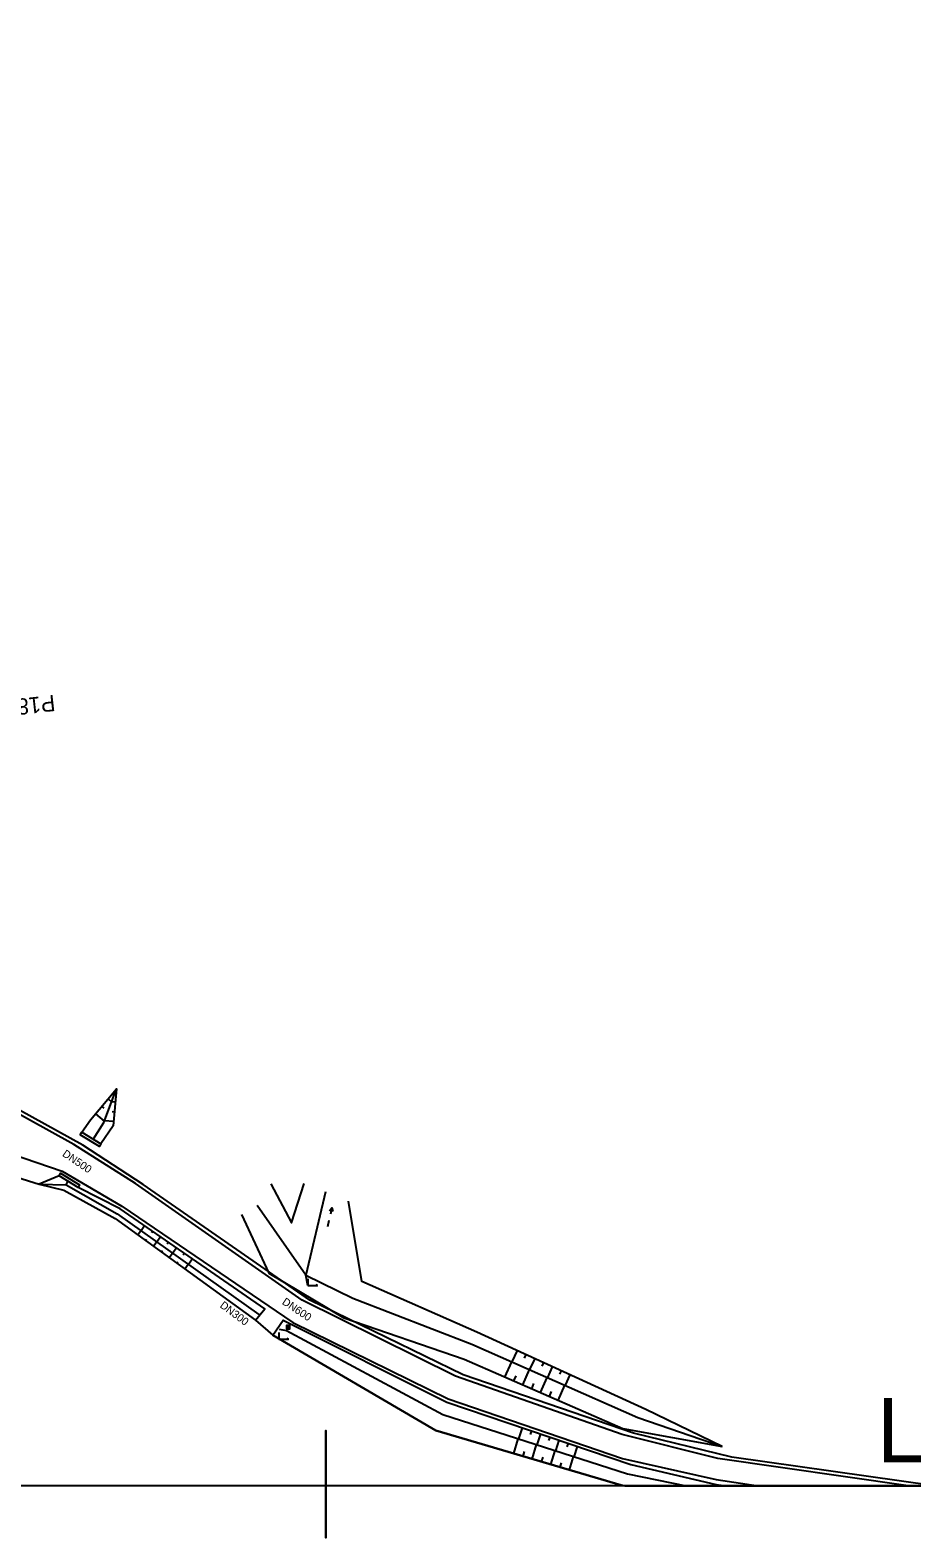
# Model space of a CAD drawing. Extents: x -574342 to -507939, y -1144044 to -1123894.
# Drawn here: x -508492.5 to -508356.1, y -1144043.8 to -1143810.6 of the extents above; entities that cross this region are included whole.
import ezdxf

# ---------------------------------------------------------------- set-up
doc = ezdxf.new("R2010")
doc.units = 0
for name, color, linetype in [('01_PARCELY_NAVRH_PC', 7, 'Continuous'), ('03_PC_POPIS_STAV', 7, 'Continuous'), ('15', 7, 'Continuous'), ('19', 7, 'Continuous'), ('43', 7, 'Continuous'), ('52', 7, 'Continuous'), ('55', 7, 'Continuous'), ('57', 7, 'Continuous'), ('60', 7, 'Continuous'), ('61', 7, 'Continuous'), ('Level 1', 7, 'Continuous')]:
    doc.layers.add(name, color=color, linetype=linetype)

msp = doc.modelspace()

# ---------------------------------------------------------------- linework, layer by layer
msp.add_lwpolyline([(-508446.76, -1144027.14), (-508446.76, -1144027.14), (-508446.76, -1144043.76), (-508446.76, -1144043.76)], close=True)
msp.add_lwpolyline([(-508446.76, -1144027.14), (-508446.76, -1144027.14), (-508446.76, -1144043.76), (-508446.76, -1144043.76)], close=True)
at = {"layer": '01_PARCELY_NAVRH_PC'}
msp.add_line((-508400.5, -1144035.7), (-508352.57, -1144035.7), dxfattribs=at)
for points in [[(-508352.57, -1144035.7), (-508383.92, -1144031.28), (-508399.15, -1144027.55), (-508425.48, -1144018.52), (-508449.21, -1144007), (-508475, -1143989.08), (-508484.35, -1143983.03), (-508505.5, -1143971.38)], [(-508500.67, -1143986.05), (-508491.07, -1143989.03), (-508487.29, -1143989.98), (-508479.33, -1143994.34), (-508457.64, -1144010.1), (-508454.94, -1144012.4), (-508429.75, -1144027.17), (-508401.07, -1144035.61), (-508400.5, -1144035.7)]]:
    msp.add_lwpolyline(points, dxfattribs=at)
at = {"layer": '43'}
for p, q in [((-508445.81, -1143992.73), (-508446.04, -1143993.7)), ((-508446.27, -1143994.67), (-508446.5, -1143995.65))]:
    msp.add_line(p, q, dxfattribs=at)
msp.add_lwpolyline([(-508446.16, -1143993.16), (-508445.81, -1143992.73), (-508445.68, -1143993.27)], dxfattribs=at)
at = {"layer": '52'}
for p, q in [((-508449.54, -1144003.7), (-508449.54, -1144004.7)), ((-508449.54, -1144004.7), (-508448.04, -1144004.7)), ((-508448.04, -1144004.7), (-508448.29, -1144004.6)), ((-508448.04, -1144004.7), (-508448.29, -1144004.8)), ((-508454.04, -1144012), (-508454.04, -1144013)), ((-508454.04, -1144013), (-508452.54, -1144013)), ((-508452.82, -1144011.17), (-508452.32, -1144011.17)), ((-508452.54, -1144013), (-508452.79, -1144012.9)), ((-508452.54, -1144013), (-508452.79, -1144013.1))]:
    msp.add_line(p, q, dxfattribs=at)
msp.add_lwpolyline([(-508452.82, -1144011.42), (-508452.32, -1144011.42), (-508452.32, -1144010.92), (-508452.82, -1144010.92)], close=True, dxfattribs=at)
at = {"layer": '55'}
for points in [[(-508356.68, -1144035.7), (-508386.12, -1144031.46), (-508400.9, -1144027.79), (-508426.7, -1144018.73), (-508450.39, -1144006.99), (-508476.21, -1143988.97), (-508485.71, -1143982.94), (-508506.36, -1143971.52), (-508511.83, -1143966.66), (-508520.4, -1143955.08), (-508524.66, -1143946.72), (-508527.67, -1143936.89)], [(-508356.68, -1144035.7), (-508386.12, -1144031.46), (-508400.9, -1144027.79), (-508426.7, -1144018.73), (-508450.39, -1144006.99), (-508476.21, -1143988.97), (-508485.71, -1143982.94), (-508506.36, -1143971.52), (-508511.83, -1143966.66), (-508520.4, -1143955.08), (-508524.66, -1143946.72), (-508527.67, -1143936.89)], [(-508494.55, -1144035.7), (-508500.53, -1144003.94), (-508501.48, -1143990.48), (-508500.5, -1143985.91), (-508495.36, -1143984.38), (-508487.51, -1143987.06), (-508478.31, -1143992.46), (-508451.87, -1144010.46), (-508427.81, -1144022.28), (-508400.84, -1144031.49), (-508386.35, -1144034.74), (-508379.88, -1144035.7)], [(-508494.55, -1144035.7), (-508500.53, -1144003.94), (-508501.48, -1143990.48), (-508500.5, -1143985.91), (-508495.36, -1143984.38), (-508487.51, -1143987.06), (-508478.31, -1143992.46), (-508451.87, -1144010.46), (-508427.81, -1144022.28), (-508400.84, -1144031.49), (-508386.35, -1144034.74), (-508379.88, -1144035.7)]]:
    msp.add_lwpolyline(points, dxfattribs=at)
at = {"layer": '57'}
for points in [[(-508484.75, -1143981.4), (-508484.5, -1143981.01), (-508481.54, -1143982.82), (-508481.77, -1143983.21)], [(-508484.75, -1143981.4), (-508484.5, -1143981.01), (-508481.54, -1143982.82), (-508481.77, -1143983.21)], [(-508488.01, -1143987.76), (-508487.79, -1143987.34), (-508484.84, -1143989.15), (-508485.07, -1143989.55)], [(-508488.01, -1143987.76), (-508487.79, -1143987.34), (-508484.84, -1143989.15), (-508485.07, -1143989.55)]]:
    msp.add_lwpolyline(points, close=True, dxfattribs=at)
at = {"layer": '60'}
for points in [[(-508484.5, -1143981.01), (-508483.17, -1143979.1), (-508479.13, -1143974.33), (-508479.65, -1143980.03), (-508481.54, -1143982.82)], [(-508484.5, -1143981.01), (-508483.17, -1143979.1), (-508479.13, -1143974.33), (-508479.65, -1143980.03), (-508481.54, -1143982.82)], [(-508482.7, -1143982.05), (-508481.08, -1143979.49), (-508479.13, -1143974.33)], [(-508482.7, -1143982.05), (-508481.08, -1143979.49), (-508479.13, -1143974.33)], [(-508488.01, -1143987.76), (-508491.07, -1143989.03), (-508487.29, -1143989.98), (-508479.33, -1143994.34), (-508457.64, -1144010.1), (-508456.2, -1144008.33), (-508478.56, -1143992.86), (-508485.07, -1143989.55)], [(-508488.01, -1143987.76), (-508491.07, -1143989.03), (-508487.29, -1143989.98), (-508479.33, -1143994.34), (-508457.64, -1144010.1), (-508456.2, -1144008.33), (-508478.56, -1143992.86), (-508485.07, -1143989.55)], [(-508491.07, -1143989.03), (-508486.93, -1143989.14), (-508486.66, -1143988.63)], [(-508491.07, -1143989.03), (-508486.93, -1143989.14), (-508486.66, -1143988.63)], [(-508486.93, -1143989.14), (-508479, -1143993.65), (-508457.13, -1144009.2)], [(-508486.93, -1143989.14), (-508479, -1143993.65), (-508457.13, -1144009.2)], [(-508455.24, -1143989.01), (-508452.07, -1143995.01), (-508450.12, -1143988.95)], [(-508455.24, -1143989.01), (-508452.07, -1143995.01), (-508450.12, -1143988.95)], [(-508446.77, -1143990.23), (-508449.82, -1144003.12), (-508442.59, -1144006.66), (-508424.18, -1144013.79), (-508398.46, -1144025.13), (-508385.42, -1144029.63)], [(-508446.77, -1143990.23), (-508449.82, -1144003.12), (-508442.59, -1144006.66), (-508424.18, -1144013.79), (-508398.46, -1144025.13), (-508385.42, -1144029.63)], [(-508385.42, -1144029.63), (-508397.26, -1144023.91), (-508423.4, -1144011.92), (-508441.15, -1144004.09), (-508443.23, -1143991.68)], [(-508385.42, -1144029.63), (-508397.26, -1144023.91), (-508423.4, -1144011.92), (-508441.15, -1144004.09), (-508443.23, -1143991.68)], [(-508459.81, -1143993.72), (-508455.54, -1144002.83), (-508443.94, -1144009.73), (-508425.37, -1144016.1), (-508400.82, -1144026.86), (-508385.42, -1144029.63)], [(-508459.81, -1143993.72), (-508455.54, -1144002.83), (-508443.94, -1144009.73), (-508425.37, -1144016.1), (-508400.82, -1144026.86), (-508385.42, -1144029.63)], [(-508449.54, -1144004.7), (-508449.82, -1144003.12), (-508457.37, -1143992.34)], [(-508449.54, -1144004.7), (-508449.82, -1144003.12), (-508457.37, -1143992.34)], [(-508454.94, -1144012.4), (-508453.34, -1144010.07), (-508428.03, -1144022.77), (-508399.55, -1144032.43), (-508386.38, -1144035.48), (-508384.8, -1144035.7)], [(-508454.94, -1144012.4), (-508453.34, -1144010.07), (-508428.03, -1144022.77), (-508399.55, -1144032.43), (-508386.38, -1144035.48), (-508384.8, -1144035.7)], [(-508400.5, -1144035.7), (-508401.07, -1144035.61), (-508429.75, -1144027.17), (-508454.94, -1144012.4)], [(-508400.5, -1144035.7), (-508401.07, -1144035.61), (-508429.75, -1144027.17), (-508454.94, -1144012.4)], [(-508453.94, -1144011.46), (-508452.82, -1144011.66), (-508452.57, -1144011.17)], [(-508453.94, -1144011.46), (-508452.82, -1144011.66), (-508452.57, -1144011.17)], [(-508452.82, -1144011.66), (-508428.63, -1144024.66), (-508400.09, -1144033.88), (-508390.99, -1144035.7)], [(-508452.82, -1144011.66), (-508428.63, -1144024.66), (-508400.09, -1144033.88), (-508390.99, -1144035.7)]]:
    msp.add_lwpolyline(points, dxfattribs=at)
at = {"layer": '61'}
for p, q in [((-508481.4, -1143977.02), (-508481.09, -1143977.28)), ((-508481.4, -1143977.02), (-508481.09, -1143977.28)), ((-508480.43, -1143975.87), (-508479.89, -1143976.33)), ((-508480.43, -1143975.87), (-508479.89, -1143976.33)), ((-508479.32, -1143976.39), (-508479.89, -1143976.34)), ((-508479.32, -1143976.39), (-508479.89, -1143976.34)), ((-508479.45, -1143977.89), (-508479.78, -1143977.86)), ((-508479.45, -1143977.89), (-508479.78, -1143977.86)), ((-508482.37, -1143978.16), (-508481.01, -1143979.31)), ((-508482.37, -1143978.16), (-508481.01, -1143979.31)), ((-508479.59, -1143979.38), (-508480.99, -1143979.25)), ((-508479.59, -1143979.38), (-508480.99, -1143979.25)), ((-508475.83, -1143996.88), (-508475.36, -1143996.24)), ((-508475.83, -1143996.88), (-508475.36, -1143996.24)), ((-508474.78, -1143995.48), (-508475.32, -1143996.26)), ((-508474.78, -1143995.48), (-508475.32, -1143996.26)), ((-508473.54, -1143996.33), (-508473.73, -1143996.6)), ((-508473.54, -1143996.33), (-508473.73, -1143996.6)), ((-508474.62, -1143997.76), (-508474.46, -1143997.54)), ((-508474.62, -1143997.76), (-508474.46, -1143997.54)), ((-508473.41, -1143998.64), (-508472.92, -1143997.97)), ((-508473.41, -1143998.64), (-508472.92, -1143997.97)), ((-508472.31, -1143997.18), (-508472.88, -1143998)), ((-508472.31, -1143997.18), (-508472.88, -1143998)), ((-508471.08, -1143998.04), (-508471.27, -1143998.32)), ((-508471.08, -1143998.04), (-508471.27, -1143998.32)), ((-508469.84, -1143998.89), (-508470.43, -1143999.74)), ((-508469.84, -1143998.89), (-508470.43, -1143999.74)), ((-508472.19, -1143999.53), (-508472.03, -1143999.3)), ((-508472.19, -1143999.53), (-508472.03, -1143999.3)), ((-508470.98, -1144000.41), (-508470.47, -1143999.71)), ((-508470.98, -1144000.41), (-508470.47, -1143999.71)), ((-508469.77, -1144001.29), (-508469.59, -1144001.05)), ((-508469.77, -1144001.29), (-508469.59, -1144001.05)), ((-508468.61, -1143999.74), (-508468.81, -1144000.03)), ((-508468.61, -1143999.74), (-508468.81, -1144000.03)), ((-508467.38, -1144000.6), (-508467.99, -1144001.48)), ((-508467.38, -1144000.6), (-508467.99, -1144001.48)), ((-508468.55, -1144002.17), (-508468.03, -1144001.45)), ((-508468.55, -1144002.17), (-508468.03, -1144001.45)), ((-508417.16, -1144014.78), (-508417.96, -1144016.53)), ((-508417.16, -1144014.78), (-508417.96, -1144016.53)), ((-508419.03, -1144018.88), (-508417.99, -1144016.52)), ((-508419.03, -1144018.88), (-508417.99, -1144016.52)), ((-508415.8, -1144015.41), (-508416.06, -1144015.98)), ((-508415.8, -1144015.41), (-508416.06, -1144015.98)), ((-508414.43, -1144016.03), (-508415.22, -1144017.74)), ((-508414.43, -1144016.03), (-508415.22, -1144017.74)), ((-508413.07, -1144016.66), (-508413.33, -1144017.22)), ((-508413.07, -1144016.66), (-508413.33, -1144017.22)), ((-508411.71, -1144017.28), (-508412.47, -1144018.95)), ((-508411.71, -1144017.28), (-508412.47, -1144018.95)), ((-508417.65, -1144019.48), (-508417.31, -1144018.7)), ((-508417.65, -1144019.48), (-508417.31, -1144018.7)), ((-508416.28, -1144020.08), (-508415.25, -1144017.73)), ((-508416.28, -1144020.08), (-508415.25, -1144017.73)), ((-508414.9, -1144020.69), (-508414.56, -1144019.9)), ((-508414.9, -1144020.69), (-508414.56, -1144019.9)), ((-508413.53, -1144021.29), (-508412.5, -1144018.94)), ((-508413.53, -1144021.29), (-508412.5, -1144018.94)), ((-508410.34, -1144017.91), (-508410.59, -1144018.46)), ((-508410.34, -1144017.91), (-508410.59, -1144018.46)), ((-508408.98, -1144018.53), (-508409.73, -1144020.16)), ((-508408.98, -1144018.53), (-508409.73, -1144020.16)), ((-508412.16, -1144021.89), (-508411.81, -1144021.11)), ((-508412.16, -1144021.89), (-508411.81, -1144021.11)), ((-508410.78, -1144022.49), (-508409.76, -1144020.15)), ((-508410.78, -1144022.49), (-508409.76, -1144020.15)), ((-508416.37, -1144026.73), (-508416.95, -1144028.43)), ((-508416.37, -1144026.73), (-508416.95, -1144028.43)), ((-508417.67, -1144030.72), (-508417, -1144028.42)), ((-508417.67, -1144030.72), (-508417, -1144028.42)), ((-508414.95, -1144027.21), (-508415.14, -1144027.77)), ((-508414.95, -1144027.21), (-508415.14, -1144027.77)), ((-508414.8, -1144031.57), (-508414.14, -1144029.34)), ((-508414.8, -1144031.57), (-508414.14, -1144029.34)), ((-508413.53, -1144027.69), (-508414.09, -1144029.36)), ((-508413.53, -1144027.69), (-508414.09, -1144029.36)), ((-508412.11, -1144028.17), (-508412.29, -1144028.72)), ((-508412.11, -1144028.17), (-508412.29, -1144028.72)), ((-508410.69, -1144028.65), (-508411.24, -1144030.28)), ((-508410.69, -1144028.65), (-508411.24, -1144030.28)), ((-508409.27, -1144029.13), (-508409.45, -1144029.67)), ((-508409.27, -1144029.13), (-508409.45, -1144029.67)), ((-508416.24, -1144031.15), (-508416.01, -1144030.39)), ((-508416.24, -1144031.15), (-508416.01, -1144030.39)), ((-508413.36, -1144031.99), (-508413.14, -1144031.26)), ((-508413.36, -1144031.99), (-508413.14, -1144031.26)), ((-508411.92, -1144032.42), (-508411.28, -1144030.26)), ((-508411.92, -1144032.42), (-508411.28, -1144030.26)), ((-508409.04, -1144033.26), (-508408.43, -1144031.19)), ((-508409.04, -1144033.26), (-508408.43, -1144031.19)), ((-508407.84, -1144029.62), (-508408.38, -1144031.2)), ((-508407.84, -1144029.62), (-508408.38, -1144031.2)), ((-508410.48, -1144032.84), (-508410.27, -1144032.14)), ((-508410.48, -1144032.84), (-508410.27, -1144032.14))]:
    msp.add_line(p, q, dxfattribs=at)
at = {"layer": 'Level 1'}
msp.add_lwpolyline([(-508026.76, -1142847.7), (-508026.76, -1144035.7), (-508866.76, -1144035.7), (-508866.76, -1142847.7)], close=True, dxfattribs=at)

# ---------------------------------------------------------------- texts
at = {"layer": '03_PC_POPIS_STAV'}
msp.add_text('LC1', height=10, dxfattribs=at).set_placement((-508361.52, -1144032.1))
at = {"layer": '15'}
for s, rotation, p in [('DN500', 325.9557, (-508487.61, -1143984.62)), ('DN500', 325.9557, (-508487.61, -1143984.62)), ('DN300', 323.1482, (-508463.24, -1144008.01)), ('DN300', 323.1482, (-508463.24, -1144008.01)), ('DN600', 326.1849, (-508453.62, -1144007.52)), ('DN600', 326.1849, (-508453.62, -1144007.52))]:
    msp.add_text(s, height=1.2, rotation=rotation, dxfattribs=at).set_placement(p)
at = {"layer": '19'}
msp.add_text('P18   900.00', height=2.5, rotation=186.3372, dxfattribs=at).set_placement((-508488.76, -1143913.36))

doc.saveas('drawing.dxf')
